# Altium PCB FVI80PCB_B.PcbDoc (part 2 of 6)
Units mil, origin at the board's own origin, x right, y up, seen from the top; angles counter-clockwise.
Board outline 3540 x 3115 mil, 12 copper layers (Top Layer, Int1(GND), Int2(Signal), Int3(GND), Int4(Signal), Int5 (GND&PW), Int6 (GND&PW), Int7(Signal), Int8(GND), Int9(Signal), Int10(GND), Bottom Layer), stack 77.136 mil thick; 488 components, 321 nets, 1809 pads, 882 vias.
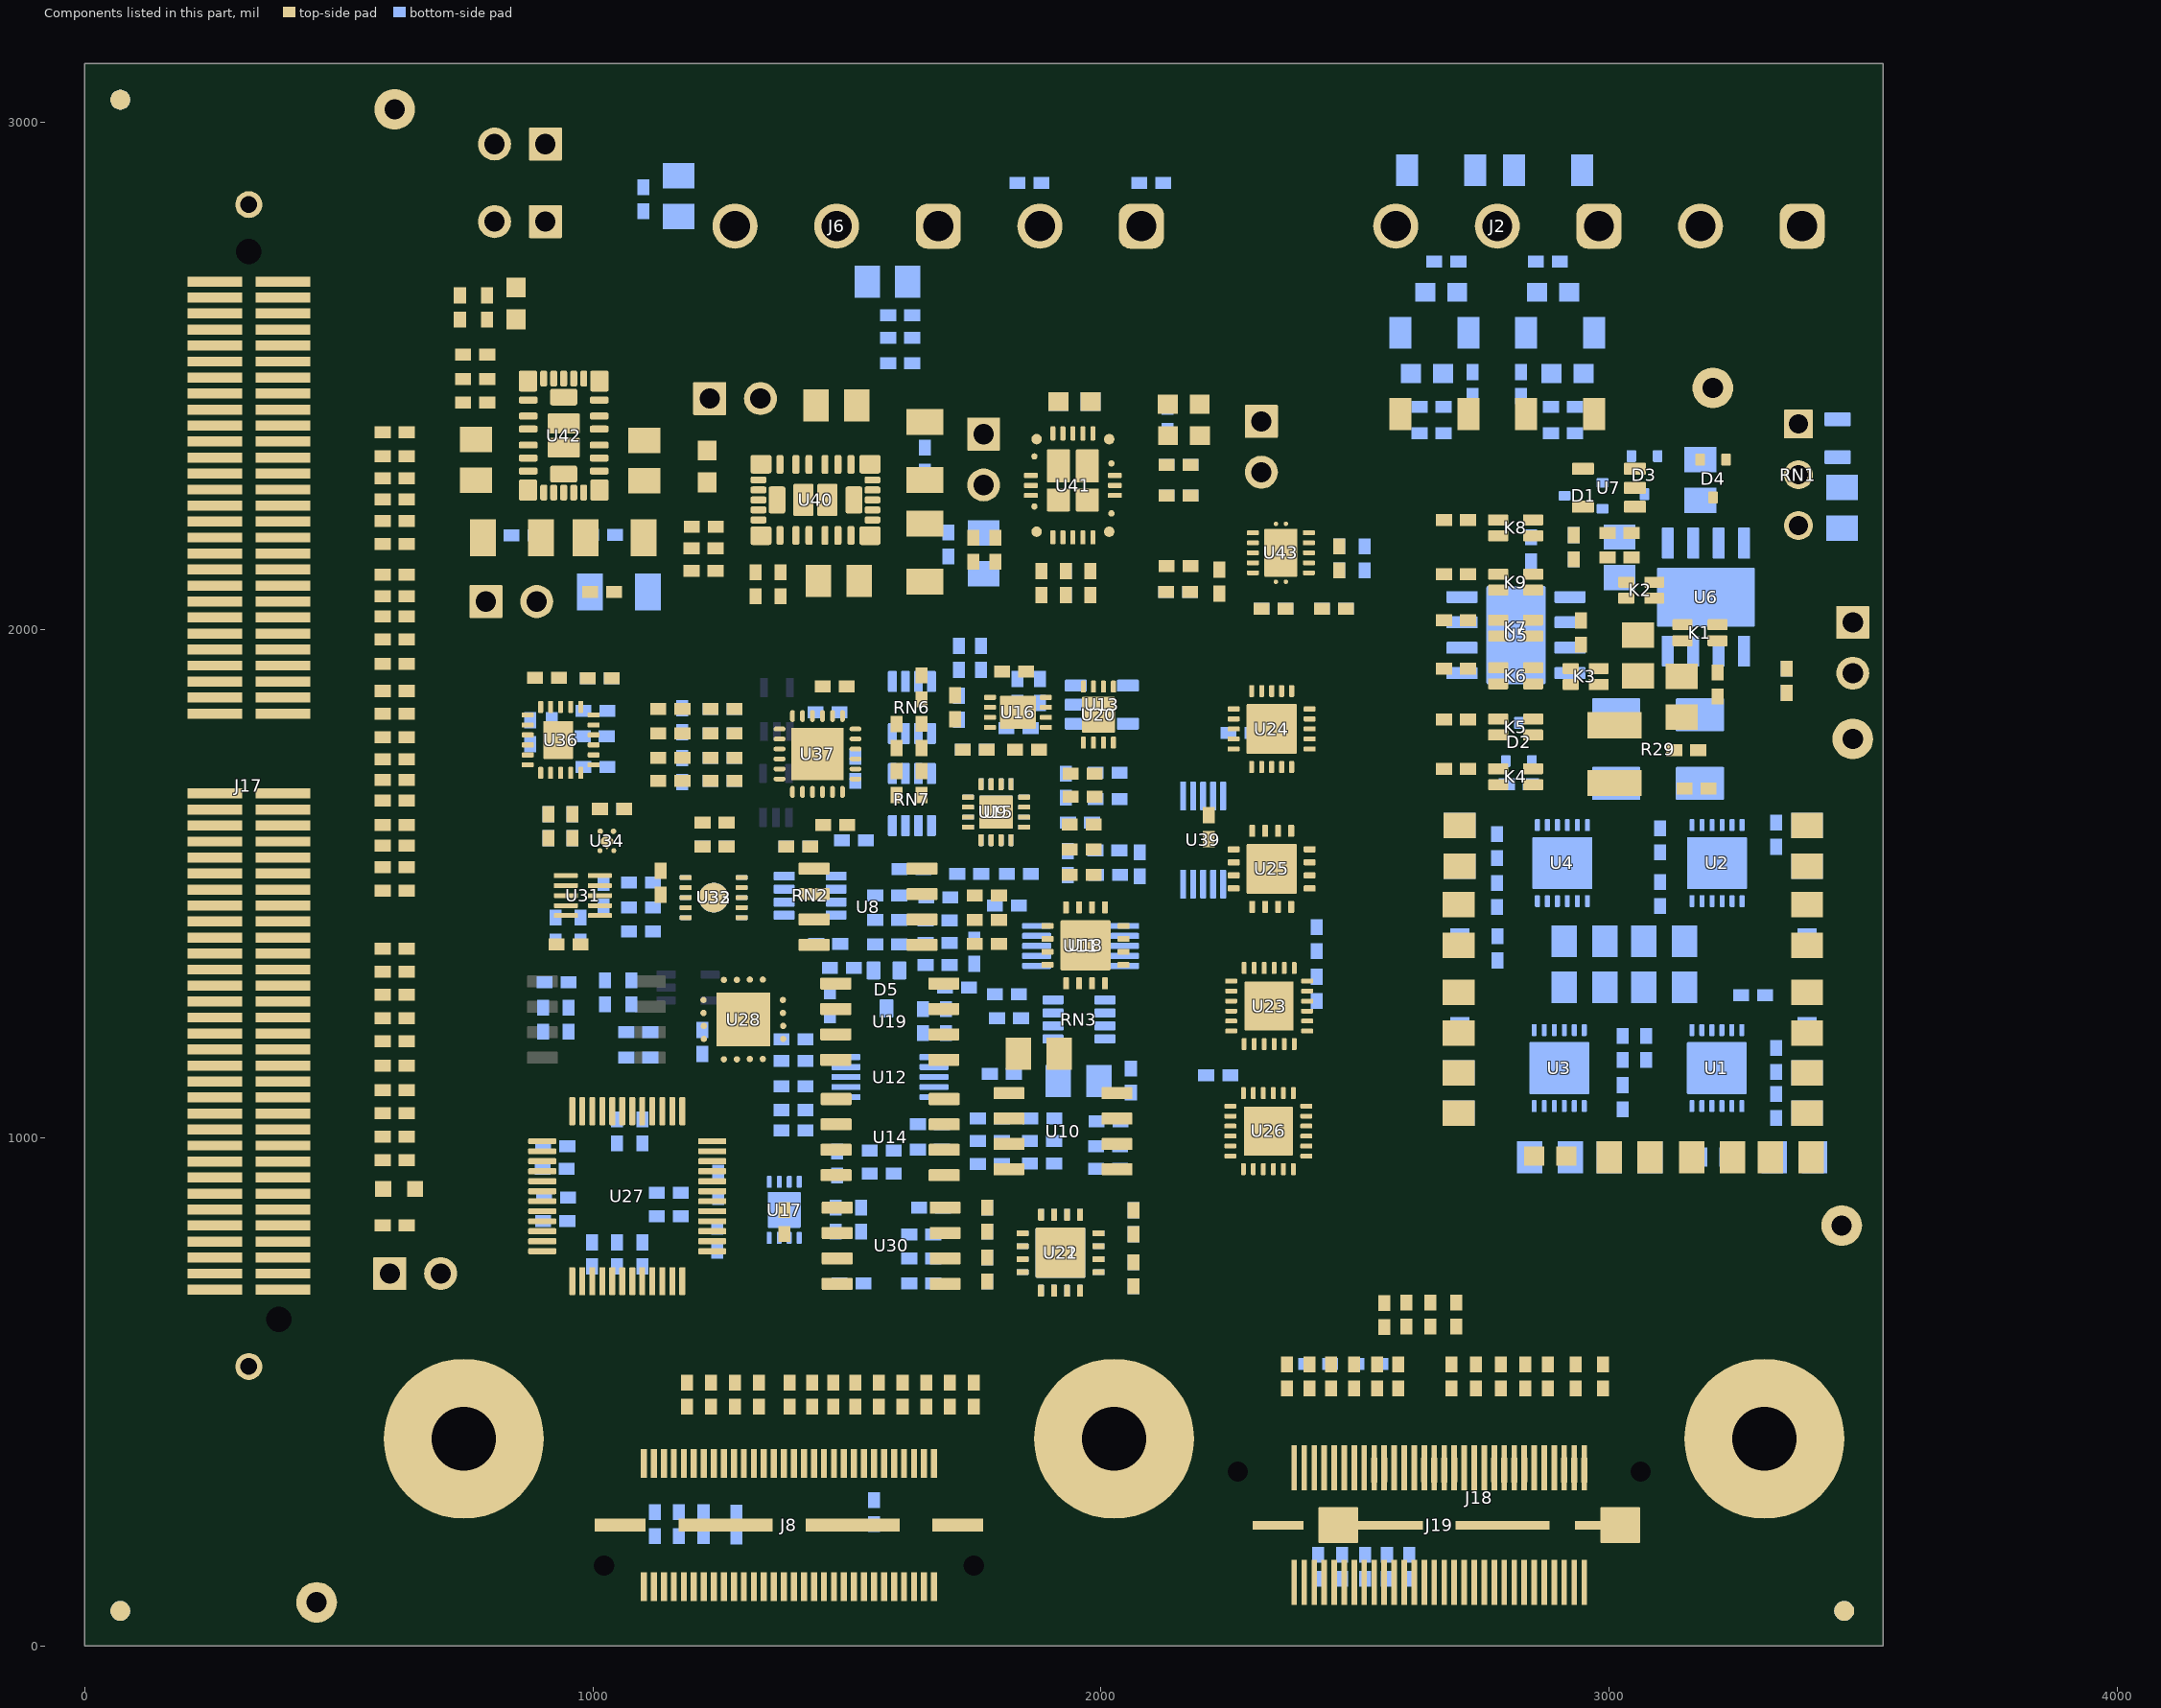
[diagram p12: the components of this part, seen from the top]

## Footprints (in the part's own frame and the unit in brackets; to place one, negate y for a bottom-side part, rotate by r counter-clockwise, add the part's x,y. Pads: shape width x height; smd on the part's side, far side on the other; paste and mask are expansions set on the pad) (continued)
DNT0012B-MFG [mm]
  rrect40% 0.6x0.25 smd paste+0 mask+0: 1(-1.9,1.25) 2(-1.9,0.75) 3(-1.9,0.25) 4(-1.9,-0.25) 5(-1.9,-0.75) 6(-1.9,-1.25) 7(1.9,-1.25) 8(1.9,-0.75) 9(1.9,-0.25) 10(1.9,0.25) 11(1.9,0.75) 12(1.9,1.25)
  rrect4% 2.6x3 smd paste-1000 mask+0: 13(0,0)
  silkscreen extent -2.87,-2.05 2.05,2.05, body extent -2,-2 2,2, height 1
DQN0004A-MFG [mm]
  round 0.279 smd paste-1000 mask-1000: 1(-0.505,0.33) 2(-0.505,-0.33)
  round 0.251 smd paste-1000 mask-1000: 3(0.459,-0.346) 4(0.459,0.346)
  rrect17% 0.58x0.58 smd rot 135 paste-1000 mask-1000: 5(0,0)
  Top Layer region: -0.66,-0.485 -0.2,-0.485 -0.2,-0.385 -0.41,-0.175 -0.66,-0.175
  Top Layer region: 0.66,0.485 0.2,0.485 0.2,0.385 0.41,0.175 0.66,0.175
  Top Layer region: 0.66,-0.485 0.2,-0.485 0.2,-0.385 0.41,-0.175 0.66,-0.175
  Top Layer region: -0.66,0.485 -0.2,0.485 -0.2,0.385 -0.41,0.175 -0.66,0.175
  silkscreen extent -1.35,-0.9 0.53,0.9, body extent -0.5,-0.5 0.5,0.5, height 0.4
DRC0010J-MFG [mm] "Recommended Land Pattern"
  rrect42% 0.6x0.24 smd paste+0 mask+0: 1(-1.4,1) 2(-1.4,0.5) 3(-1.4,0) 4(-1.4,-0.5) 5(-1.4,-1) 6(1.4,-1) 7(1.4,-0.5) 8(1.4,0) 9(1.4,0.5) 10(1.4,1)
  round 1.485 smd paste-1000 mask+0: 11(0,0)
  Top Layer region: -0.825,-1.15 -0.818,-1.175 -0.8,-1.193 -0.775,-1.2 -0.775,-1.2 -0.375,-1.2 -0.375,-1.65 -0.368,-1.675 -0.35,-1.693 -0.325,-1.7 -0.325,-1.7 -0.175,-1.7 -0.156,-1.696 -0.14,-1.685 -0.129,-1.669 -0.125,-1.65 -0.125,-1.65 -0.125,-1.2 0.125,-1.2 0.125,-1.65 0.129,-1.669 0.14,-1.685 0.156,-1.696 0.175,-1.7 0.175,-1.7 0.325,-1.7 0.35,-1.693 0.368,-1.675 0.375,-1.65 0.375,-1.65 0.375,-1.2 0.775,-1.2 0.8,-1.193 0.818,-1.175 0.825,-1.15 0.825,-1.15 0.825,1.15 0.818,1.175 0.8,1.193 0.775,1.2 0.775,1.2 0.375,1.2 0.375,1.65 0.368,1.675 0.35,1.693 0.325,1.7 0.325,1.7 0.175,1.7 0.156,1.696 0.14,1.685 0.129,1.669 0.125,1.65 0.125,1.65 0.125,1.2 -0.125,1.2 -0.125,1.65 -0.129,1.669 -0.14,1.685 -0.156,1.696 -0.175,1.7 -0.175,1.7 -0.325,1.7 -0.35,1.693 -0.368,1.675 -0.375,1.65 -0.375,1.65 -0.375,1.2 -0.775,1.2 -0.8,1.193 -0.818,1.175 -0.825,1.15 -0.825,1.15
  silkscreen extent -2.38,-1.55 1.55,1.55, body extent -1.5,-1.5 1.5,1.5, height 1
DRX0010A [mm] "WSON-10"
  rrect33% 1.2x0.24 smd: 1(-0.85,1) 2(-0.85,0.5) 3(-0.85,0) 4(-0.85,-0.5) 5(-0.85,-1) 6(0.85,-1) 7(0.85,-0.5) 8(0.85,0) 9(0.85,0.5) 10(0.85,1)
  silkscreen extent -1.8,-1.6 1.8,1.6, body extent -1.3,-1.3 1.3,1.3, height 0.81
DSC0010J-MFG [mm]
  rrect42% 0.6x0.24 smd paste+0 mask+0: 1(-1.4,1) 2(-1.4,0.5) 3(-1.4,0) 4(-1.4,-0.5) 5(-1.4,-1) 6(1.4,-1) 7(1.4,-0.5) 8(1.4,0) 9(1.4,0.5) 10(1.4,1)
  round 0.225 smd paste-1000 mask+0: 11(-0.25,-1.45) 11(-0.25,1.448) 11(0.25,-1.448) 11(0.25,1.45)
  rrect6% 1.65x2.4 smd paste-1000 mask+0: 11(0,0)
  Top Layer region: -0.375,1.2 -0.375,1.65 -0.371,1.669 -0.36,1.685 -0.344,1.696 -0.325,1.7 -0.325,1.7 -0.175,1.7 -0.156,1.696 -0.14,1.685 -0.129,1.669 -0.125,1.65 -0.125,1.65 -0.125,1.2
  Top Layer region: 0.125,1.2 0.125,1.65 0.129,1.669 0.14,1.685 0.156,1.696 0.175,1.7 0.175,1.7 0.325,1.7 0.344,1.696 0.36,1.685 0.371,1.669 0.375,1.65 0.375,1.65 0.375,1.2
  Top Layer region: -0.125,-1.2 -0.125,-1.65 -0.132,-1.675 -0.15,-1.693 -0.175,-1.7 -0.175,-1.7 -0.325,-1.7 -0.344,-1.696 -0.36,-1.685 -0.371,-1.669 -0.375,-1.65 -0.375,-1.65 -0.375,-1.2
  Top Layer region: 0.375,-1.2 0.375,-1.65 0.371,-1.669 0.36,-1.685 0.344,-1.696 0.325,-1.7 0.325,-1.7 0.175,-1.7 0.156,-1.696 0.14,-1.685 0.129,-1.669 0.125,-1.65 0.125,-1.65 0.125,-1.2
  silkscreen extent -2.4,-1.55 1.55,1.55, body extent -1.8,-1.8 1.8,1.8, height 0.25
FCC_disclaimer [mil]
Fiducial10-20 [mm]
  round 1 smd mask+0.5: 1(0,0)
  Top Layer keep-out circle w1.178: c0,0 r0.5
FP-CRCW08055K00FKTA_0805-MFG [mm]
  rrect14% 0.7x1.3 smd paste+0 mask+0: 1(-0.95,0) 2(0.95,0)
  silkscreen extent -0.23,-0.7 0.23,0.7, body extent -1,-0.63 1,0.63, height 0.5
FP-SBAV99WT1G_SOT-323-3-419-04-MFG [mm]
  rrect14% 0.9x0.7 smd paste+0 mask+0: 1(-0.95,0.65) 2(-0.95,-0.65) 3(0.95,0)
  silkscreen extent -0.13,-1.1 0.67,1.1, body extent -1.05,-1.05 1.05,1.05, height 1
FP-TLP3420(TP,F_SMD4-MFG [mm]
  rrect18% 0.55x1 smd paste+0 mask+0: 1(-0.4,-0.875) 2(0.4,-0.875) 3(0.4,0.875) 4(-0.4,0.875)
  silkscreen extent -1.07,-2.08 1.07,1.58, body extent -0.85,-1.48 0.85,1.48, height 0.25
FP-Y0115V0030VV9L_RADIAL-MFG [mm] "Recommended Land Pattern"
  rrect7% 1.45x1.45 hole 0.95 paste-2539.97 mask+0: 1(-2.54,0)
  round 1.45 hole 0.95 paste-2539.97 mask+0: 2(0,0) 3(2.54,0)
  silkscreen extent -5.15,-1.85 4.55,1.85, body extent -4.45,-1.75 4.45,1.75, height 10.7
FP-Y08502R00000F9R_2516-MFG [mm] "Recommended Land Pattern"
  rrect6% 2.41x1.65 smd paste+0 mask+0: E1(-2.095,1.715) E2(-2.095,-1.715) I1(2.095,1.715) I2(2.095,-1.715)
  silkscreen extent -4,-2.15 3.3,2.15, body extent -3.18,-2.03 3.18,2.03, height 1.02
Keystone5000 [mil] "For Keystone 500x miniature loop terminals"
  round 80 hole 40: 1(0,0)
  silkscreen extent -52,-52 52,52, body extent -49,-49 49,49, height 182
Keystone5001 [mil] "For Keystone 500x miniature loop terminals"
  round 80 hole 40: 1(0,0)
  silkscreen extent -52,-52 52,52, body extent -49,-49 49,49, height 182
Label_650x200 [mil] "Thermal Transfer Label"
  round 1 on Mech14: 0(0,0)
  silkscreen extent -325,-100 325,100, body extent -325,-100 325,100, height 1
"NY PMS 440 0025 PH" [mm] "4-40 nylon screw and mounting hole"
  round 8 / inner round 3.556 / far side round 8 hole 3.2: 1(0,0)
  body extent -3.3,-3.3 3.3,3.3, height 2.69
Omron_S-VSON4 [mm] "SMD, 4-Leads, Body 2x1.45mm"
  rrect18% 0.8x0.55 smd: 1(-0.65,0.4) 2(-0.65,-0.4)
  rrect18% 1x0.55 smd: 3(0.75,-0.4) 4(0.75,0.4)
  silkscreen extent -0.7,0.9 -0.6,1, body extent -0.9,-0.72 1.1,0.73, height 1.65
PFB0048A-MFG [mm]
  rrect33% 1.4x0.3 smd paste-1000 mask+0: 1(-4.25,2.75) 2(-4.25,2.25) 3(-4.25,1.75) 4(-4.25,1.25) 5(-4.25,0.75) 6(-4.25,0.25) 7(-4.25,-0.25) 8(-4.25,-0.75) 9(-4.25,-1.25) 10(-4.25,-1.75) 11(-4.25,-2.25) 12(-4.25,-2.75) 25(4.25,-2.75) 26(4.25,-2.25) 27(4.25,-1.75) 28(4.25,-1.25) 29(4.25,-0.75) 30(4.25,-0.25) 31(4.25,0.25) 32(4.25,0.75) 33(4.25,1.25) 34(4.25,1.75) 35(4.25,2.25) 36(4.25,2.75)
  rrect33% 0.3x1.4 smd paste-1000 mask+0: 13(-2.75,-4.25) 14(-2.25,-4.25) 15(-1.75,-4.25) 16(-1.25,-4.25) 17(-0.75,-4.25) 18(-0.25,-4.25) 19(0.25,-4.25) 20(0.75,-4.25) 21(1.25,-4.25) 22(1.75,-4.25) 23(2.25,-4.25) 24(2.75,-4.25) 37(2.75,4.25) 38(2.25,4.25) 39(1.75,4.25) 40(1.25,4.25) 41(0.75,4.25) 42(0.25,4.25) 43(-0.25,4.25) 44(-0.75,4.25) 45(-1.25,4.25) 46(-1.75,4.25) 47(-2.25,4.25) 48(-2.75,4.25)
  silkscreen extent -5.63,-3.6 3.6,3.6, body extent -5.05,-5.05 5.05,5.05, height 0.25
RDH0030A-MFG [mm]
  rrect22% 0.93x1.05 smd paste-1000 mask-1000: 1(-1.786,2.725) 8(-1.786,-2.725) 14(1.786,-2.725) 21(1.786,2.725)
  rrect57% 0.95x0.35 smd paste-1000 mask-1000: 2(-1.775,1.775) 3(-1.775,0.975) 4(-1.775,0.325) 5(-1.775,-0.475) 6(-1.775,-1.125) 7(-1.775,-1.775) 15(1.775,-1.775) 16(1.775,-1.125) 17(1.775,-0.475) 18(1.775,0.325) 19(1.775,0.975) 20(1.775,1.775)
  rrect57% 0.35x0.8 smd paste-1000 mask-1000: 9(-1,-2.85) 10(-0.5,-2.85) 11(0,-2.85) 12(0.5,-2.85) 13(1,-2.85) 22(1,2.85) 23(0.5,2.85) 24(0,2.85) 25(-0.5,2.85) 26(-1,2.85)
  rrect24% 1.35x0.84 smd paste-1000 mask-1000: 27(0,1.925) 30(0,-1.925)
  rrect10% 1.6x1 smd paste-1000 mask-1000: 28(0,0.6) 29(0,-0.6)
  Top Layer region: -0.85,1.05 -0.837,1.1 -0.8,1.137 -0.75,1.15 -0.75,1.15 0.75,1.15 0.8,1.137 0.837,1.1 0.85,1.05 0.85,1.05 0.85,-1.05 0.837,-1.1 0.8,-1.137 0.75,-1.15 0.75,-1.15 -0.75,-1.15 -0.8,-1.137 -0.837,-1.1 -0.85,-1.05 -0.85,-1.05
  silkscreen extent -2.95,-3.65 2.05,3.65, body extent -2.35,-3.35 2.35,3.35, height 0.25
RDU0028A-MFG [mm]
  round 0.52 smd paste+0 mask+0: 1(-1.814,2.314) 7(-1.814,-2.314) 13(1.814,-2.314) 19(1.814,2.314)
  round 0.315 smd paste+0 mask+0: 2(-1.925,1.4) 6(-1.925,-1.1) 14(1.925,-1.45) 18(1.925,1.05)
  rrect40% 0.7x0.25 smd paste+0 mask+0: 3(-2.1,0.5) 4(-2.1,0) 5(-2.1,-0.5) 15(2.1,-0.5) 16(2.1,0) 17(2.1,0.5)
  rrect40% 0.25x0.7 smd paste+0 mask+0: 8(-1,-2.6) 9(-0.5,-2.6) 10(0,-2.6) 11(0.5,-2.6) 12(1,-2.6) 20(1,2.6) 21(0.5,2.6) 22(0,2.6) 23(-0.5,2.6) 24(-1,2.6)
  rrect9% 1.15x1.15 smd paste-1000 mask+0: 25(-0.725,0.725) 28(0.725,0.725)
  rrect9% 1.15x1.65 smd paste-1000 mask+0: 26(-0.725,-0.975) 27(0.725,-0.975)
  Top Layer region: 2.4,0.875 1.8,0.875 1.775,0.882 1.757,0.9 1.75,0.925 1.75,0.925 1.75,1.575 1.754,1.594 1.765,1.61 1.781,1.621 1.8,1.625 1.8,1.625 2.4,1.625 2.419,1.621 2.435,1.61 2.446,1.594 2.45,1.575 2.45,1.575 2.45,1.425 2.443,1.4 2.425,1.382 2.4,1.375 2.4,1.375 2.225,1.375 2.187,1.367 2.154,1.346 2.133,1.313 2.125,1.275 2.125,1.275 2.125,1.225 2.138,1.175 2.175,1.138 2.225,1.125 2.225,1.125 2.4,1.125 2.419,1.121 2.435,1.11 2.446,1.094 2.45,1.075 2.45,1.075 2.45,0.925 2.443,0.9 2.425,0.882 2.4,0.875
  Top Layer region: 2.4,-1.625 1.8,-1.625 1.775,-1.618 1.757,-1.6 1.75,-1.575 1.75,-1.575 1.75,-0.925 1.754,-0.906 1.765,-0.89 1.781,-0.879 1.8,-0.875 1.8,-0.875 2.4,-0.875 2.419,-0.879 2.435,-0.89 2.446,-0.906 2.45,-0.925 2.45,-0.925 2.45,-1.075 2.443,-1.1 2.425,-1.118 2.4,-1.125 2.4,-1.125 2.225,-1.125 2.187,-1.133 2.154,-1.154 2.133,-1.187 2.125,-1.225 2.125,-1.225 2.125,-1.275 2.138,-1.325 2.175,-1.362 2.225,-1.375 2.225,-1.375 2.4,-1.375 2.419,-1.379 2.435,-1.39 2.446,-1.406 2.45,-1.425 2.45,-1.425 2.45,-1.575 2.443,-1.6 2.425,-1.618 2.4,-1.625
  Top Layer region: -2.4,-0.875 -1.8,-0.875 -1.775,-0.882 -1.757,-0.9 -1.75,-0.925 -1.75,-0.925 -1.75,-1.575 -1.754,-1.594 -1.765,-1.61 -1.781,-1.621 -1.8,-1.625 -1.8,-1.625 -2.4,-1.625 -2.419,-1.621 -2.435,-1.61 -2.446,-1.594 -2.45,-1.575 -2.45,-1.575 -2.45,-1.425 -2.443,-1.4 -2.425,-1.382 -2.4,-1.375 -2.4,-1.375 -2.225,-1.375 -2.187,-1.367 -2.154,-1.346 -2.133,-1.313 -2.125,-1.275 -2.125,-1.275 -2.125,-1.225 -2.138,-1.175 -2.175,-1.138 -2.225,-1.125 -2.225,-1.125 -2.4,-1.125 -2.419,-1.121 -2.435,-1.11 -2.446,-1.094 -2.45,-1.075 -2.45,-1.075 -2.45,-0.925 -2.443,-0.9 -2.425,-0.882 -2.4,-0.875
  Top Layer region: -2.4,1.625 -1.8,1.625 -1.781,1.621 -1.765,1.61 -1.754,1.594 -1.75,1.575 -1.75,1.575 -1.75,0.925 -1.754,0.906 -1.765,0.89 -1.781,0.879 -1.8,0.875 -1.8,0.875 -2.4,0.875 -2.419,0.879 -2.435,0.89 -2.446,0.906 -2.45,0.925 -2.45,0.925 -2.45,1.075 -2.443,1.1 -2.425,1.118 -2.4,1.125 -2.4,1.125 -2.225,1.125 -2.187,1.133 -2.154,1.154 -2.133,1.187 -2.125,1.225 -2.125,1.225 -2.125,1.275 -2.138,1.325 -2.175,1.362 -2.225,1.375 -2.225,1.375 -2.4,1.375 -2.419,1.379 -2.435,1.39 -2.446,1.406 -2.45,1.425 -2.45,1.425 -2.45,1.575 -2.443,1.6 -2.425,1.618 -2.4,1.625
  Top Layer region: 1.575,2.95 1.55,2.943 1.532,2.925 1.525,2.9 1.525,2.9 1.525,2.075 1.529,2.056 1.54,2.04 1.556,2.029 1.575,2.025 1.575,2.025 2.4,2.025 2.423,2.033 2.439,2.051 2.445,2.075 2.445,2.075 2.45,2.225 2.443,2.25 2.425,2.268 2.4,2.275 2.4,2.275 2.225,2.275 2.187,2.283 2.154,2.304 2.133,2.337 2.125,2.375 2.125,2.375 2.125,2.575 2.118,2.6 2.1,2.618 2.075,2.625 2.075,2.625 1.875,2.625 1.837,2.633 1.804,2.654 1.783,2.687 1.775,2.725 1.775,2.725 1.775,2.9 1.768,2.925 1.75,2.943 1.725,2.95 1.725,2.95
  Top Layer region: 1.575,-2.95 1.55,-2.943 1.532,-2.925 1.525,-2.9 1.525,-2.9 1.525,-2.075 1.529,-2.056 1.54,-2.04 1.556,-2.029 1.575,-2.025 1.575,-2.025 2.4,-2.025 2.423,-2.033 2.439,-2.051 2.445,-2.075 2.445,-2.075 2.45,-2.225 2.443,-2.25 2.425,-2.268 2.4,-2.275 2.4,-2.275 2.225,-2.275 2.187,-2.283 2.154,-2.304 2.133,-2.337 2.125,-2.375 2.125,-2.375 2.125,-2.575 2.118,-2.6 2.1,-2.618 2.075,-2.625 2.075,-2.625 1.875,-2.625 1.837,-2.633 1.804,-2.654 1.783,-2.687 1.775,-2.725 1.775,-2.725 1.775,-2.9 1.768,-2.925 1.75,-2.943 1.725,-2.95 1.725,-2.95
  Top Layer region: -1.575,-2.95 -1.55,-2.943 -1.532,-2.925 -1.525,-2.9 -1.525,-2.9 -1.525,-2.075 -1.529,-2.056 -1.54,-2.04 -1.556,-2.029 -1.575,-2.025 -1.575,-2.025 -2.4,-2.025 -2.423,-2.033 -2.439,-2.051 -2.445,-2.075 -2.445,-2.075 -2.45,-2.225 -2.443,-2.25 -2.425,-2.268 -2.4,-2.275 -2.4,-2.275 -2.225,-2.275 -2.187,-2.283 -2.154,-2.304 -2.133,-2.337 -2.125,-2.375 -2.125,-2.375 -2.125,-2.575 -2.118,-2.6 -2.1,-2.618 -2.075,-2.625 -2.075,-2.625 -1.875,-2.625 -1.837,-2.633 -1.804,-2.654 -1.783,-2.687 -1.775,-2.725 -1.775,-2.725 -1.775,-2.9 -1.768,-2.925 -1.75,-2.943 -1.725,-2.95 -1.725,-2.95
  Top Layer region: -1.575,2.95 -1.55,2.943 -1.532,2.925 -1.525,2.9 -1.525,2.9 -1.525,2.075 -1.529,2.056 -1.54,2.04 -1.556,2.029 -1.575,2.025 -1.575,2.025 -2.4,2.025 -2.423,2.033 -2.439,2.051 -2.445,2.075 -2.445,2.075 -2.45,2.225 -2.443,2.25 -2.425,2.268 -2.4,2.275 -2.4,2.275 -2.225,2.275 -2.187,2.283 -2.154,2.304 -2.133,2.337 -2.125,2.375 -2.125,2.375 -2.125,2.575 -2.118,2.6 -2.1,2.618 -2.075,2.625 -2.075,2.625 -1.875,2.625 -1.837,2.633 -1.804,2.654 -1.783,2.687 -1.775,2.725 -1.775,2.725 -1.775,2.9 -1.768,2.925 -1.75,2.943 -1.725,2.95 -1.725,2.95
  silkscreen extent -3.2,-3.13 2.63,3.13, body extent -2.55,-3.05 2.55,3.05, height 0.25
RGT0016J-MFG [mm]
  rrect40% 0.6x0.25 smd paste+0 mask+0: 1(-1.4,0.75) 2(-1.4,0.25) 3(-1.4,-0.25) 4(-1.4,-0.75) 9(1.4,-0.75) 10(1.4,-0.25) 11(1.4,0.25) 12(1.4,0.75)
  rrect40% 0.25x0.6 smd paste+0 mask+0: 5(-0.75,-1.4) 6(-0.25,-1.4) 7(0.25,-1.4) 8(0.75,-1.4) 13(0.75,1.4) 14(0.25,1.4) 15(-0.25,1.4) 16(-0.75,1.4)
  rrect6% 1.66x1.66 smd paste-1000 mask+0: 17(0,0)
  silkscreen extent -2.37,-1.55 1.55,1.55, body extent -1.5,-1.5 1.5,1.5, height 1
RQX0008A-MFG [mm] "Recommended Land Pattern"
  rrect40% 0.6x0.25 smd paste+0 mask+0: 1(-1.4,0.75) 2(-1.4,0.25) 3(-1.4,-0.25) 4(-1.4,-0.75) 5(1.4,-0.75) 6(1.4,-0.25) 7(1.4,0.25) 8(1.4,0.75)
  rrect6% 1.8x1.65 smd paste-1000 mask+0: 9(0,0)
  silkscreen extent -2.45,-1.33 1.5,1.33, body extent -1.5,-1 1.5,1, height 0.8
RRQ0020A-MFG [mm]
  rrect40% 0.6x0.25 smd paste+0 mask+0: 1(-1.9,1) 2(-1.9,0.5) 3(-1.9,0) 4(-1.9,-0.5) 5(-1.9,-1) 11(1.9,-1) 12(1.9,-0.5) 13(1.9,0) 14(1.9,0.5) 15(1.9,1)
  rrect40% 0.25x0.6 smd paste+0 mask+0: 6(-1,-1.9) 7(-0.5,-1.9) 8(0,-1.9) 9(0.5,-1.9) 10(1,-1.9) 16(1,1.9) 17(0.5,1.9) 18(0,1.9) 19(-0.5,1.9) 20(-1,1.9)
  rrect4% 2.5x2.5 smd paste-1000 mask+0: 21(0,0)
  silkscreen extent -2.88,-2.05 2.05,2.05, body extent -2.3,-2.3 2.3,2.3, height 0.25
RTW0024A [mm] "QFN, 24-Leads, Body 4x4mm, Pitch 0.5mm, Thermal Pad 2.6x2.6mm, TI Recommended"
  oval 0.6x0.24 smd: 1(-1.9,1.25) 2(-1.9,0.75) 3(-1.9,0.25) 4(-1.9,-0.25) 5(-1.9,-0.75) 6(-1.9,-1.25) 13(1.9,-1.25) 14(1.9,-0.75) 15(1.9,-0.25) 16(1.9,0.25) 17(1.9,0.75) 18(1.9,1.25)
  oval 0.24x0.6 smd: 7(-1.25,-1.9) 8(-0.75,-1.9) 9(-0.25,-1.9) 10(0.25,-1.9) 11(0.75,-1.9) 12(1.25,-1.9) 19(1.25,1.9) 20(0.75,1.9) 21(0.25,1.9) 22(-0.25,1.9) 23(-0.75,1.9) 24(-1.25,1.9)
  rect 2.6x2.6 smd paste-1.3: 25(0,0)
  silkscreen extent -2.22,-2.22 2.22,2.22, body extent -2.07,-2.07 2.07,2.07, height 0.81
RTW0024B-MFG [mm]
  rrect42% 0.6x0.24 smd paste+0 mask+0: 1(-1.9,1.25) 2(-1.9,0.75) 3(-1.9,0.25) 4(-1.9,-0.25) 5(-1.9,-0.75) 6(-1.9,-1.25) 13(1.9,-1.25) 14(1.9,-0.75) 15(1.9,-0.25) 16(1.9,0.25) 17(1.9,0.75) 18(1.9,1.25)
  rrect42% 0.24x0.6 smd paste+0 mask+0: 7(-1.25,-1.9) 8(-0.75,-1.9) 9(-0.25,-1.9) 10(0.25,-1.9) 11(0.75,-1.9) 12(1.25,-1.9) 19(1.25,1.9) 20(0.75,1.9) 21(0.25,1.9) 22(-0.25,1.9) 23(-0.75,1.9) 24(-1.25,1.9)
  rrect4% 2.45x2.45 smd paste-1000 mask+0: 25(0,0)
  silkscreen extent -2.9,-2.05 2.05,2.05, body extent -2.3,-2.3 2.3,2.3, height 0.25
RUM0016B-MFG [mm] "Recommended Land Pattern"
  round 0.315 smd paste-1000 mask+0: 1(-1.993,0.975) 2(-1.993,0.325) 3(-1.975,-0.325) 4(-1.975,-0.975) 5(-0.975,-1.993) 6(-0.325,-1.993) 7(0.325,-1.975) 8(0.975,-1.975) 9(1.993,-0.975) 10(1.993,-0.325) 11(1.975,0.325) 12(1.975,0.975) 13(0.975,1.993) 14(0.325,1.993) 15(-0.325,1.975) 16(-0.975,1.975)
  rrect4% 2.7x2.7 smd paste-1000 mask+0: 17(0,0)
  Top Layer region: -2.4,1.15 -1.725,1.15 -1.658,1.137 -1.601,1.099 -1.563,1.042 -1.55,0.975 -1.55,0.975 -1.563,0.908 -1.601,0.851 -1.658,0.813 -1.725,0.8 -1.725,0.8 -2.4,0.8
  Top Layer region: -2.4,0.5 -1.725,0.5 -1.658,0.487 -1.601,0.449 -1.563,0.392 -1.55,0.325 -1.55,0.325 -1.563,0.258 -1.601,0.201 -1.658,0.163 -1.725,0.15 -1.725,0.15 -2.4,0.15
  Top Layer region: -2.4,-0.15 -1.725,-0.15 -1.658,-0.163 -1.601,-0.201 -1.563,-0.258 -1.55,-0.325 -1.55,-0.325 -1.563,-0.392 -1.601,-0.449 -1.658,-0.487 -1.725,-0.5 -1.725,-0.5 -2.4,-0.5
  Top Layer region: -2.4,-0.8 -1.725,-0.8 -1.658,-0.813 -1.601,-0.851 -1.563,-0.908 -1.55,-0.975 -1.55,-0.975 -1.563,-1.042 -1.601,-1.099 -1.658,-1.137 -1.725,-1.15 -1.725,-1.15 -2.4,-1.15
  Top Layer region: 2.4,-1.15 1.725,-1.15 1.658,-1.137 1.601,-1.099 1.563,-1.042 1.55,-0.975 1.55,-0.975 1.563,-0.908 1.601,-0.851 1.658,-0.813 1.725,-0.8 1.725,-0.8 2.4,-0.8
  Top Layer region: 2.4,-0.5 1.725,-0.5 1.658,-0.487 1.601,-0.449 1.563,-0.392 1.55,-0.325 1.55,-0.325 1.563,-0.258 1.601,-0.201 1.658,-0.163 1.725,-0.15 1.725,-0.15 2.4,-0.15
  Top Layer region: 2.4,0.15 1.725,0.15 1.658,0.163 1.601,0.201 1.563,0.258 1.55,0.325 1.55,0.325 1.563,0.392 1.601,0.449 1.658,0.487 1.725,0.5 1.725,0.5 2.4,0.5
  Top Layer region: 2.4,0.8 1.725,0.8 1.658,0.813 1.601,0.851 1.563,0.908 1.55,0.975 1.55,0.975 1.563,1.042 1.601,1.099 1.658,1.137 1.725,1.15 1.725,1.15 2.4,1.15
  Top Layer region: -1.15,-2.4 -1.15,-1.725 -1.137,-1.658 -1.099,-1.601 -1.042,-1.563 -0.975,-1.55 -0.975,-1.55 -0.908,-1.563 -0.851,-1.601 -0.813,-1.658 -0.8,-1.725 -0.8,-1.725 -0.8,-2.4
  Top Layer region: -0.5,-2.4 -0.5,-1.725 -0.487,-1.658 -0.449,-1.601 -0.392,-1.563 -0.325,-1.55 -0.325,-1.55 -0.258,-1.563 -0.201,-1.601 -0.163,-1.658 -0.15,-1.725 -0.15,-1.725 -0.15,-2.4
  Top Layer region: 0.15,-2.4 0.15,-1.725 0.163,-1.658 0.201,-1.601 0.258,-1.563 0.325,-1.55 0.325,-1.55 0.392,-1.563 0.449,-1.601 0.487,-1.658 0.5,-1.725 0.5,-1.725 0.5,-2.4
  Top Layer region: 0.8,-2.4 0.8,-1.725 0.813,-1.658 0.851,-1.601 0.908,-1.563 0.975,-1.55 0.975,-1.55 1.042,-1.563 1.099,-1.601 1.137,-1.658 1.15,-1.725 1.15,-1.725 1.15,-2.4
  Top Layer region: 1.15,2.4 1.15,1.725 1.137,1.658 1.099,1.601 1.042,1.563 0.975,1.55 0.975,1.55 0.908,1.563 0.851,1.601 0.813,1.658 0.8,1.725 0.8,1.725 0.8,2.4
  Top Layer region: 0.5,2.4 0.5,1.725 0.487,1.658 0.449,1.601 0.392,1.563 0.325,1.55 0.325,1.55 0.258,1.563 0.201,1.601 0.163,1.658 0.15,1.725 0.15,1.725 0.15,2.4
  Top Layer region: -0.15,2.4 -0.15,1.725 -0.163,1.658 -0.201,1.601 -0.258,1.563 -0.325,1.55 -0.325,1.55 -0.392,1.563 -0.449,1.601 -0.487,1.658 -0.5,1.725 -0.5,1.725 -0.5,2.4
  Top Layer region: -0.8,2.4 -0.8,1.725 -0.813,1.658 -0.851,1.601 -0.908,1.563 -0.975,1.55 -0.975,1.55 -1.042,1.563 -1.099,1.601 -1.137,1.658 -1.15,1.725 -1.15,1.725 -1.15,2.4
  Top Layer keep-out region: -2,1.5 -1.5,1.5 -1.5,2 -2,2
  silkscreen extent -3.07,-2.05 2.05,2.05, body extent -2,-2 2,2, height 0.8
RUM0016E-MFG#1 [mm]
  rrect33% 0.6x0.3 smd paste+0 mask+0: 1(-1.9,0.975) 2(-1.9,0.325) 3(-1.9,-0.325) 4(-1.9,-0.975) 9(1.9,-0.975) 10(1.9,-0.325) 11(1.9,0.325) 12(1.9,0.975)
  rrect33% 0.3x0.6 smd paste+0 mask+0: 5(-0.975,-1.9) 6(-0.325,-1.9) 7(0.325,-1.9) 8(0.975,-1.9) 13(0.975,1.9) 14(0.325,1.9) 15(-0.325,1.9) 16(-0.975,1.9)
  rrect4% 2.5x2.5 smd paste-25.4 mask+0: 17(0,0)
  silkscreen extent -2.9,-2.05 2.05,2.05, body extent -2,-2 2,2, height 0.8
RUM0016E-MFG#2 [mm]
  rrect33% 0.6x0.3 smd paste+0 mask+0: 1(-1.9,0.975) 2(-1.9,0.325) 3(-1.9,-0.325) 4(-1.9,-0.975) 9(1.9,-0.975) 10(1.9,-0.325) 11(1.9,0.325) 12(1.9,0.975)
  rrect33% 0.3x0.6 smd paste+0 mask+0: 5(-0.975,-1.9) 6(-0.325,-1.9) 7(0.325,-1.9) 8(0.975,-1.9) 13(0.975,1.9) 14(0.325,1.9) 15(-0.325,1.9) 16(-0.975,1.9)
  rrect4% 2.5x2.5 smd paste-1000 mask+0: 17(0,0)
  silkscreen extent -2.9,-2.05 2.05,2.05, body extent -2,-2 2,2, height 0.8
Samtec_HTSW-102-07-G-S [mm] "Samtec 100mil, 1x2, 230 mil above insulator"
  rrect6% 1.65x1.65 hole 1.016: 1(-1.27,0)
  round 1.65 hole 1.016: 2(1.27,0)
  silkscreen extent -3.3,-1.27 2.54,1.27, body extent -2.54,-1.27 2.54,1.27, height 8.38
Samtec_QSH-030-01-X-D-A [mm] "Receptacle, 0.5 mm, 30x2, TH"
  rect 2.27x0.279 smd: 1(-2.865,7.25) 2(2.865,7.25) 3(-2.865,6.75) 4(2.865,6.75) 5(-2.865,6.25) 6(2.865,6.25) 7(-2.865,5.75) 8(2.865,5.75) 9(-2.865,5.25) 10(2.865,5.25) 11(-2.865,4.75) 12(2.865,4.75) 13(-2.865,4.25) 14(2.865,4.25) 15(-2.865,3.75) 16(2.865,3.75) 17(-2.865,3.25) 18(2.865,3.25) 19(-2.865,2.75) 20(2.865,2.75) 21(-2.865,2.25) 22(2.865,2.25) 23(-2.865,1.75) 24(2.865,1.75) 25(-2.865,1.25) 26(2.865,1.25) 27(-2.865,0.75) 28(2.865,0.75) 29(-2.865,0.25) 30(2.865,0.25) 31(-2.865,-0.25) 32(2.865,-0.25) 33(-2.865,-0.75) 34(2.865,-0.75) 35(-2.865,-1.25) 36(2.865,-1.25) 37(-2.865,-1.75) 38(2.865,-1.75) 39(-2.865,-2.25) 40(2.865,-2.25) 41(-2.865,-2.75) 42(2.865,-2.75) 43(-2.865,-3.25) 44(2.865,-3.25) 45(-2.865,-3.75) 46(2.865,-3.75) 47(-2.865,-4.25) 48(2.865,-4.25) 49(-2.865,-4.75) 50(2.865,-4.75) 51(-2.865,-5.25) 52(2.865,-5.25) 53(-2.865,-5.75) 54(2.865,-5.75) 55(-2.865,-6.25) 56(2.865,-6.25) 57(-2.865,-6.75) 58(2.865,-6.75) 59(-2.865,-7.25) 60(2.865,-7.25)
  round 0 hole 1.02 unplated: MH1(2.67,10.065) MH2(2.67,-10.065)
  rect 0.43x2.54 smd: MP1(0,8.065) MP4(0,-8.065)
  rect 0.43x4.7 smd: MP2(0,3.175) MP3(0,-3.175)
  silkscreen extent -3.9,-10.66 3.62,10.66, body extent -3.75,-10.64 3.75,10.67, height 3.25
Samtec_QTH-030-01-x-D-A [mil] "Header (Shrouded), 19.7mil, 30x2, SMT"
  rect 12x57 smd: 1(-285.7,121.5) 2(-285.7,-121.5) 3(-266,121.5) 4(-266,-121.5) 5(-246.3,121.5) 6(-246.3,-121.5) 7(-226.6,121.5) 8(-226.6,-121.5) 9(-206.9,121.5) 10(-206.9,-121.5) 11(-187.2,121.5) 12(-187.2,-121.5) 13(-167.5,121.5) 14(-167.5,-121.5) 15(-147.8,121.5) 16(-147.8,-121.5) 17(-128.1,121.5) 18(-128.1,-121.5) 19(-108.4,121.5) 20(-108.4,-121.5) 21(-88.7,121.5) 22(-88.7,-121.5) 23(-69,121.5) 24(-69,-121.5) 25(-49.3,121.5) 26(-49.3,-121.5) 27(-29.6,121.5) 28(-29.6,-121.5) 29(-9.9,121.5) 30(-9.9,-121.5) 31(9.8,121.5) 32(9.8,-121.5) 33(29.5,121.5) 34(29.5,-121.5) 35(49.2,121.5) 36(49.2,-121.5) 37(68.9,121.5) 38(68.9,-121.5) 39(88.6,121.5) 40(88.6,-121.5) 41(108.3,121.5) 42(108.3,-121.5) 43(128,121.5) 44(128,-121.5) 45(147.7,121.5) 46(147.7,-121.5) 47(167.4,121.5) 48(167.4,-121.5) 49(187.1,121.5) 50(187.1,-121.5) 51(206.8,121.5) 52(206.8,-121.5) 53(226.5,121.5) 54(226.5,-121.5) 55(246.2,121.5) 56(246.2,-121.5) 57(265.9,121.5) 58(265.9,-121.5) 59(285.6,121.5) 60(285.6,-121.5)
  round 0 hole 40 unplated: MH1(-364,80) MH2(364,80)
  rect 100x25 smd: MP1(-332.7,0) MP4(332.3,0)
  rect 185x25 smd: MP2(-125.2,0) MP3(124.8,0)
  silkscreen extent -394,-118 394,131, body extent -394,-140 394,140, height 170
SOT-323 [mm] "Diodes Inc recommended land pattern.  2016-02-24"
  rrect21% 0.6x0.47 smd: 1(-0.95,0.65) 2(-0.95,-0.65) 3(0.95,0)
  silkscreen extent -1.14,-1.22 0.77,1.22, body extent -1.13,-1.13 1.12,1.12, height 1.13
TI_Stacked_Overlay_Small [mil]
  silkscreen extent -418,-98 418,98
VAE0022A-MFG [mm]
  rrect40% 0.6x0.25 smd paste+0 mask+0: 1(-1.65,1.25) 2(-1.65,0.75) 3(-1.65,0.25) 4(-1.65,-0.25) 5(-1.65,-0.75) 6(-1.65,-1.25) 12(1.65,-1.25) 13(1.65,-0.75) 14(1.65,-0.25) 15(1.65,0.25) 16(1.65,0.75) 17(1.65,1.25)
  rrect40% 0.25x0.6 smd paste+0 mask+0: 7(-1,-1.65) 8(-0.5,-1.65) 9(0,-1.65) 10(0.5,-1.65) 11(1,-1.65) 18(1,1.65) 19(0.5,1.65) 20(0,1.65) 21(-0.5,1.65) 22(-1,1.65)
  rrect7% 1.5x1.895 smd paste-1000 mask+0: 23(0.123,0)
  silkscreen extent -2.63,-1.8 1.8,1.8, body extent -2.05,-2.05 2.05,2.05, height 0.25
WEEE_Minimum [mil] "WEEElie bin"
  silkscreen extent -95,-172 99,104
WL-SMCW_GREEN [mm] "WURTH"
  rect 0.8x0.8 smd: 1(-0.8,0) 2(0.8,0)
  silkscreen extent -1.9,-0.8 1.2,0.8, body extent -0.85,-0.45 0.85,0.45, height 0.8
Wurth_60900213421 [mil] "Shunt, 2.54mm, Black"
  round 1 on Mech3: 0(0,0)
  body extent -98,-48 98,48, height 338
Wurth_687122149022 [mm] "FPC Connector, 0.5mm, 22 Pos, R/A, SMT"
  rrect33% 0.3x1.3 smd: 1(-5.25,2.75) 2(-4.75,2.75) 3(-4.25,2.75) 4(-3.75,2.75) 5(-3.25,2.75) 6(-2.75,2.75) 7(-2.25,2.75) 8(-1.75,2.75) 9(-1.25,2.75) 10(-0.75,2.75) 11(-0.25,2.75) 12(0.25,2.75) 13(0.75,2.75) 14(1.25,2.75) 15(1.75,2.75) 16(2.25,2.75) 17(2.75,2.75) 18(3.25,2.75) 19(3.75,2.75) 20(4.25,2.75) 21(4.75,2.75) 22(5.25,2.75)
  rrect6% 2x1.8 smd: MP1(-7.05,0) MP2(7.05,0)
  body extent -7.55,-3.5 7.55,3, height 2.25
Wurth_691236510002 [mm] "Terminal Block, 5.08mm, 2x1, R/A, TH"
  rrect50% 2.25x2.25 hole 1.5: 1(-2.54,0)
  round 2.25 hole 1.5: 2(2.54,0)
  body extent -5.68,-5.5 5.08,5.85, height 18
Wurth_691236510003 [mm] "Terminal Block, 5.08mm, 3x1, R/A, TH"
  rrect50% 2.25x2.25 hole 1.5: 1(-5.08,0)
  round 2.25 hole 1.5: 2(0,0) 3(5.08,0)
  body extent -8.22,-5.5 7.62,5.85, height 18

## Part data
C1 C2 C3 C4 C5 C6 C7 C8 C10 C11 C15 C16 C141 C143: library part CMP-0006618-2, "CAP, CERM, 0.1 uF, 100 V, +/- 10%, X5R, 0402", Cap_Case=0402, Manufacturer=MuRata, Supplier Part Number 1=490-10458-1-ND, TempCo=X5R, Tolerance_%=10%, Value1=Unknown, Value2=100V, ValueDisplayed=0.1uF
C9 C13 C14 C18 C140 C142: library part CMP-0078499-1, "CAP, CERM, 4.7 µF, 100 V,+/- 20%, X7S, 1206", Cap_Case=1206, Manufacturer=AVX, Supplier Part Number 1=478-8719-1-ND, TempCo=X7S, Tolerance_%=20%, Value2=100V, ValueDisplayed=4.7µF
C12 C17: library part CMP-0006704-2, "CAP, CERM, 2200 pF, 100 V, +/- 10%, X7R, 0402", Cap_Case=0402, Manufacturer=MuRata, Supplier Part Number 1=GRM155R72A222KA01D-ND, TempCo=X7R, Tolerance_%=10%, Value1=Unknown, Value2=100V, ValueDisplayed=2200pF
C19 C20 C27 C28 C35 C36 C37 C38 C46 C52 C53 C56: library part CMP-0006443-2, "CAP, CERM, 27 pF, 50 V, +/- 5%, C0G/NP0, 0402", Cap_Case=0402, Manufacturer=MuRata, Supplier Part Number 1=14T3294, TempCo=C0G/NP0, Tolerance_%=5%, Value1=Unknown, Value2=50V, ValueDisplayed=27pF
C21 C22 C23 C24 C25 C26 C29 C30 C31 C32 C33 C34 C42 C43 C44 C45 C48 C49 C55 C57 C59 C60 C61 C62 C63 C64 C66 C67 C68 C69 C71 C72 C76 C78 C80 C85 C87 C89 C92 C96 C102 C104 C114 C117 C119 C120 C124 C127 C129 C131 C144 C145 C146 C147 C148 C149 C150: library part CMP-0080610-1, "CAP, CERM, 0.1 µF, 25 V,+/- 10%, X7R, AEC-Q200 Grade 1, 0402", Cap_Case=0402, Manufacturer=TDK, Supplier Part Number 1=445-6902-1-ND, TempCo=X7R, Tolerance_%=10%, Value2=25V, ValueDisplayed=0.1µF
C39 C86 C88 C91 C94 C95 C97 C98 C105 C109 C115 C122 C130 C134 C151 C152: library part CMP-0860997-1, "CAP, CERM, 1000 pF, 50 V,+/- 10%, X8R, AEC-Q200 Grade 0, 0402", Cap_Case=0402, Manufacturer=TDK, TempCo=X8R, Tolerance_%=10%, Value2=50V, ValueDisplayed=1000pF
C40 C106 C108 C133: library part CMP-0006674-2, "CAP, CERM, 0.01 uF, 50 V, +/- 10%, X7R, 0402", Cap_Case=0402, Manufacturer=MuRata, Supplier Part Number 1=490-4516-1-ND, TempCo=X7R, Tolerance_%=10%, Value1=Unknown, Value2=50V, ValueDisplayed=0.01uF
C41: library part CMP-0064928-2, "CAP, CERM, 0.47 uF, 25 V,+/- 10%, X5R, 0402", Cap_Case=0402, Manufacturer=MuRata, Supplier Part Number 1=490-14365-1-ND, TempCo=X5R, Tolerance_%=10%, Value1=Unknown, Value2=25V, ValueDisplayed=0.47uF
C47 C50 C51 C54 C58 C65 C70 C75 C77 C79 C90 C93 C116 C118 C128 C137: library part CMP-0006564-3, "CAP, CERM, 10 uF, 10 V, +/- 20%, X5R, 0402", Cap_Case=0402, Manufacturer=MuRata, TempCo=X5R, Tolerance_%=20%, Value1=Unknown, Value2=10V, ValueDisplayed=10uF
C99 C121: library part CMP-0081259-1, "CAP, CERM, 1 µF, 35 V,+/- 10%, X7R, AEC-Q200 Grade 1, 0603", Cap_Case=0603, Manufacturer=TDK, Supplier Part Number 1=445-174339-1-ND, TempCo=X7R, Tolerance_%=10%, Value2=35V, ValueDisplayed=1µF
C100 C101 C123 C125 C126: library part CMP-0008646-2, "CAP, CERM, 47 uF, 25 V, +/- 20%, JB, 1206", Cap_Case=1206, Manufacturer=TDK, Supplier Part Number 1=445-11717-1-ND, TempCo=JB, Tolerance_%=20%, Value1=Unknown, Value2=25V, ValueDisplayed=47uF
C103 C107 C132 C138 C139: library part CMP-0084680-1, "CAP, CERM, 22 µF, 25 V,+/- 20%, X5R, AEC-Q200 Grade 3, 0805", Cap_Case=0805, Manufacturer=MuRata, TempCo=X5R, Tolerance_%=20%, Value2=25V, ValueDisplayed=22µF
C110 C111 C112 C113: library part CMP-0081159-1, "CAP, CERM, 22 µF, 16 V,+/- 20%, X5R, 0603", Cap_Case=0603, Manufacturer=Samsung, Supplier Part Number 1=1276-7076-1-ND, TempCo=X5R, Tolerance_%=20%, Value2=16V, ValueDisplayed=22µF
C135 C136: library part CMP-0007860-1, "CAP, CERM, 4.7 uF, 50 V, +/- 10%, X6S, 0805", Cap_Case=0805, Manufacturer=TDK, Supplier Part Number 1=445-7599-1-ND, TempCo=X6S, Tolerance_%=10%, Value1="0.002346 ohm", Value2=50V, ValueDisplayed=4.7uF
D1 D2 D3 D4: library part CMP-0006013-3, "Diode, Zener, 9.1 V, 0.18 W, AEC-Q101, SOT-323", Manufacturer="NXP Semiconductor", Power_W=180mW, Value1=0.18W
D5: library part CMP-0089118-1, "Diode Array 1 Pair Series Connection Standard 100V 215mA Surface Mount SC-70, SOT-323", Digikey Part Number=SBAV99WT1GOSCT-ND, Forward Current=215mA, Manufacturer="On Semiconductor", Max Surge Forward Current=0.5A, Mouser Part Number=863-SBAV99WT1G, Operating Temperature Range="-65°C to +150°C", Peak Reverse Current=1uA, ValueDisplayed=1.5pF
D8: library part CMP-0002894-2, "LED, Green, SMD", Color=green, Manufacturer="Wurth Elektronik", Value1=W, Value2=2V
FB1 FB2: library part CMP-0003237-1, "Ferrite Bead, 120 ohm @ 100 MHz, 1.2 A, 0402", Manufacturer="Wurth Elektronik", Supplier Part Number 1=732-2366-1-ND, Value1="0.09 ohm", Value2=1.2A, ValueDisplayed="120 ohm"
FID1 FID2 FID3 FID4 FID5 FID6: library part CMP-0077181-1, "Fiducial mark.  There is nothing to buy or mount.", Manufacturer=N/A
H1 H2 H3: library part CMP-0003617-1, "Machine Screw, Round, #4-40 x 1/4, Nylon, Philips panhead", Manufacturer="B&F Fastener Supply", Supplier Part Number 1=H542-ND
J1 J4 J5: library part CMP-0079044-1, "Terminal Block, 5.08mm, 2x1, R/A, TH", Color=Green, Current_A=20A, Manufacturer="Wurth Elektronik", Supplier Part Number 1=732-10995-ND, Voltage_V=300V
J2 J6: library part CMP-0079043-1, "Terminal Block, 5.08mm, 3x1, R/A, TH", Color=Green, Current_A=20A, Manufacturer="Wurth Elektronik", Supplier Part Number 1=732-10996-ND, Voltage_V=300V
J3 J7 J9 J10 J11 J12 J13 J14: library part CMP-0075483-1, "Header, 100mil, 2x1, Gold, TH", Manufacturer=Samtec, Supplier Part Number 1=SAM8736-ND
J8: library part CMP-0075558-1, "Header(Shrouded), 19.7mil, 30x2, Gold, SMT", Manufacturer=Samtec, Supplier Part Number 1=SAM8185-ND
J17: library part CMP-0003814-2, "C2000 controlCARD-120HSEC connector, SMT", Manufacturer=Samtec
J18: library part CMP-0081902-1, "FPC Connector, 0.5mm, 22 Pos, R/A, Tin, SMT", Color=Black, Current_A=500mA, Manufacturer="Wurth Elektronik", Supplier Part Number 1=732-6003-1-ND, Voltage_V=50V
J19: library part CMP-0075524-1, "Receptacle, 0.5 mm, 30x2, Gold, TH", Color=Black, Manufacturer=Samtec, Supplier Part Number 1=SAM8180-ND
K1 K4 K5 K6 K7 K8 K9: library part CMP-0095654-1, Digikey Part Number=TLP3420(TPFCT-ND, Input Current=7.5mA, Manufacturer=Toshiba, Mouser Part Number=757-TLP3420TPF, On State Resistance=8Ω, Operating Temperature Range="-20°C to +85°C", Voltage_Isolation_Vrms=500Vrms
K2 K3: library part CMP-0080719-2, "Relay, SPST-NO (1 Form A), 0.65 A, SMD", Contact Rating_A=650mA, Manufacturer=Toshiba, Supplier Part Number 1=TLP3409S(TPECT-ND
LBL1: library part CMP-0003625-1, "Thermal Transfer Printable Labels, 0.650\" W x 0.200\" H - 10,000 per roll", Manufacturer=Brady, Supplier Part Number 1=97C5133
Logo1: library part CMP-0074844-1
Logo2: library part CMP-0074838-1, "Texas Instrument Corporate Signature"
Logo3: library part CMP-0074847-1, "FCC_disclaimer"
Logo4: library part CMP-0074769-3, Manufacturer="Texas Instruments"
R1 R2 R18 R19: library part CMP-0021141-3, "RES, 2.00, 1%, 0.125 W, AEC-Q200 Grade 0, 0805", Manufacturer=Vishay-Dale, Power_W=125mW, Supplier Part Number 1=541-2.00CCCT-ND, TempCo="100 ppm/C", Tolerance_%=1%, Value2=0.125W, Value_Code=2R00, ValueDisplayed=2.00
R3: library part CMP-0022371-4, "RES, 3.01 k, 1%, 0.1 W, AEC-Q200 Grade 0, 0603", Manufacturer=Vishay-Dale, Power_W=100mW, Supplier Part Number 1=541-3.01KHCT-ND, TempCo="100 ppm/C", Tolerance_%=1%, Value2=0.1W, Value_Code=3k01, ValueDisplayed=3.01k
R4 R5 R6 R12 R13 R14 R15 R16 R17 R72 R73 R74 R85 R96 R97 R98 R101 R102: library part CMP-0021342-3, "RES, 59.0 k, 1%, 0.125 W, AEC-Q200 Grade 0, 0805", Manufacturer=Vishay-Dale, Power_W=125mW, Supplier Part Number 1=541-59.0KCCT-ND, TempCo="100 ppm/C", Tolerance_%=1%, Value2=0.125W, Value_Code=59k0, ValueDisplayed=59.0k
R7 R8 R11 R83 R84: library part CMP-0022268-3, "RES, 2.00 k, 1%, 0.1 W, 0603", Manufacturer=Vishay-Dale, Power_W=100mW, Supplier Part Number 1=541-2.00KHCT-ND, TempCo="100 ppm/C", Tolerance_%=1%, Value2=0.1W, Value_Code=2k00, ValueDisplayed=2.00k
R9 R10 R20 R21 R53 R65 R67 R68 R69 R70 R75 R76 R77 R78 R105 R107 R115 R116 R117 R118 R120 R125 R126 R127 R135 R150 R152 R153 R159 R160 R230: library part CMP-0026748-1, "RES, 10.0 k, 1%, 0.063 W, AEC-Q200 Grade 0, 0402", Manufacturer="KOA Speer", Power_W=63mW, Supplier Part Number 1=660-RK73H1ETTP1002F, TempCo="100 ppm/C", Tolerance_%=1%, Value2=0.063W, Value_Code=10k0, ValueDisplayed=10.0k
R22 R23 R30 R33 R34 R35 R36 R37 R38 R57 R60 R61 R64 R66 R88 R90 R112 R163 R167 R176: library part CMP-0026071-2, "RES, 1.00 k, 1%, 0.063 W, 0402", Manufacturer=Vishay-Dale, Power_W=63mW, Supplier Part Number 1=541-1.00KLCT-ND, TempCo="100 ppm/C", Tolerance_%=1%, Value2=0.063W, Value_Code=1k00, ValueDisplayed=1.00k
R24: library part CMP-0015029-2, "RES, 2.00, 1%, 0.5 W, AEC-Q200 Grade 0, 1210", Manufacturer=Panasonic, Power_W=500mW, Supplier Part Number 1=P17258CT-ND, TempCo="100 ppm/C", Tolerance_%=1%, Value2=0.5W, Value_Code=2R00, ValueDisplayed=2.00
R25: library part CMP-0020835-3, "RES, 100, 1%, 0.125 W, AEC-Q200 Grade 0, 0805", Manufacturer=Vishay-Dale, Power_W=125mW, Supplier Part Number 1=541-100CCT-ND, TempCo="100 ppm/C", Tolerance_%=1%, Value2=0.125W, Value_Code=100R, ValueDisplayed=100
R26: library part CMP-0020834-2, "RES, 100 k, 1%, 0.125 W, 0805", Manufacturer=Vishay-Dale, Power_W=125mW, Supplier Part Number 1=541-100KCCT-ND, TempCo="100 ppm/C", Tolerance_%=1%, Value2=0.125W, Value_Code=100k
R27 R28 R31 R32 R47 R48 R49 R50 R51 R54 R55 R62 R63 R71 R79 R81 R87 R89 R94 R99 R104 R114 R119 R128 R129 R134 R142 R228: library part CMP-0026822-3, "RES, 0, 5%, 0.063 W, AEC-Q200 Grade 0, 0402", Manufacturer=Vishay-Dale, Power_W=63mW, Supplier Part Number 1=541-0.0JCT-ND, TempCo="200 ppm/C", Tolerance_%=5%, Value2=0.063W, Value_Code=0000, ValueDisplayed=0
R29: library part CMP-0126086-1, "2 Ohms ±1% 0.5W, 1/2W Chip Resistor Wide 2516 (6440 Metric), 1625 Current Sense, Moisture Resistant, Non-Inductive Metal Foil", Digikey Part Number=804-1119-1-ND, Manufacturer="VPG Foil Resistors", Operating Temperature Range="-55°C to +125°C", Power_W=500mW, TempCo=2ppm/°C, Tolerance_%=1%
R39 R44: library part CMP-0021039-1, "RES, 200, 1%, 0.125 W, 0805", Manufacturer=Vishay-Dale, Power_W=125mW, Supplier Part Number 1=541-200CCT-ND, TempCo="100 ppm/C", Tolerance_%=1%, Value2=0.125W, Value_Code=200R, ValueDisplayed=200
R40 R41 R45 R46 R52 R56 R58 R59 R91 R92 R93 R95 R103 R111 R113 R121 R123 R124 R130 R138 R229 R233: library part CMP-0026763-1, "RES, 100, 1%, 0.063 W, AEC-Q200 Grade 0, 0402", Manufacturer="Stackpole Electronics Inc", Power_W=63mW, Supplier Part Number 1=RMCF0402JT100RCT-ND, TempCo="100 ppm/C", Tolerance_%=1%, Value2=0.063W, Value_Code=100R, ValueDisplayed=100
R42: library part CMP-0021721-3, "RES, 45.3 k, 1%, 0.125 W, AEC-Q200 Grade 0, 0805", Manufacturer=Panasonic, Power_W=125mW, Supplier Part Number 1=P45.3KCCT-ND, TempCo="100 ppm/C", Tolerance_%=1%, Value2=0.125W, Value_Code=45k3, ValueDisplayed=45.3k
R43: library part CMP-0088945-1, "5 kOhms ±1% 0.125W, 1/8W Chip Resistor 0805 (2012 Metric) Automotive AEC-Q200 Thick Film", Digikey Part Number=541-4321-1-ND, Manufacturer="Vishay Dale", Mouser Part Number=71-CRCW0805-5K, Operating Temperature Range="-55°C to +155°C", Power_W=125mW, TempCo=100ppm/°C, Tolerance_%=1%
R80 R82: library part CMP-0021613-3, "RES, 2.00 k, 1%, 0.125 W, AEC-Q200 Grade 0, 0805", Manufacturer=Panasonic, Power_W=125mW, Supplier Part Number 1=P2.00KCCT-ND, TempCo="100 ppm/C", Tolerance_%=1%, Value2=0.125W, Value_Code=2k00, ValueDisplayed=2.00k
R86 R161: library part CMP-0026178-1, "RES, 22.1 k, 1%, 0.063 W, 0402", Manufacturer=Vishay-Dale, Power_W=63mW, Supplier Part Number 1=541-22.1KLCT-ND, TempCo="100 ppm/C", Tolerance_%=1%, Value2=0.063W, Value_Code=22k1, ValueDisplayed=22.1k
R100 R110 R155 R204 R208: library part CMP-0026727-1, "RES, 1.00 M, 1%, 0.063 W, 0402", Manufacturer="Yageo America", Power_W=63mW, Supplier Part Number 1=311-1.00MLRCT-ND, TempCo="100 ppm/C", Tolerance_%=1%, Value2=0.063W, Value_Code=1M00, ValueDisplayed=1.00M
R106: library part CMP-0026370-1, "RES, 412, 1%, 0.063 W, 0402", Manufacturer=Vishay-Dale, Power_W=63mW, Supplier Part Number 1=541-412LCT-ND, TempCo="100 ppm/C", Tolerance_%=1%, Value2=0.063W, Value_Code=412R, ValueDisplayed=412
R108 R232: library part CMP-0026414-1, "RES, 4.99 k, 1%, 0.063 W, 0402", Manufacturer=Vishay-Dale, Power_W=63mW, Supplier Part Number 1=541-4.99KLCT-ND, TempCo="100 ppm/C", Tolerance_%=1%, Value2=0.063W, Value_Code=4k99, ValueDisplayed=4.99k
R109: library part CMP-0026227-1, "RES, 2.00 k, 1%, 0.063 W, 0402", Manufacturer=Vishay-Dale, Power_W=63mW, Supplier Part Number 1=541-2.00KLCT-ND, TempCo="100 ppm/C", Tolerance_%=1%, Value2=0.063W, Value_Code=2k00, ValueDisplayed=2.00k
R122: library part CMP-0026029-3, "RES, 15.8 k, 1%, 0.063 W, AEC-Q200 Grade 0, 0402", Manufacturer=Vishay-Dale, Power_W=63mW, Supplier Part Number 1=541-15.8KLCT-ND, TempCo="100 ppm/C", Tolerance_%=1%, Value2=0.063W, Value_Code=15k8, ValueDisplayed=15.8k
R131 R133 R137 R139 R140 R144 R146 R165 R166 R169 R170 R171 R172 R173 R174 R175 R177 R178 R179 R180 R181 R182 R183 R184 R185 R186 R187 R188 R189 R190 R191 R192 R197 R199 R201 R203 R206 R214 R215 R216 R217 R218 R219 R220 R221 R222 R223 R224 R225 R226 R227 R231: library part CMP-0025963-3, "RES, 10.0, 1%, 0.063 W, AEC-Q200 Grade 0, 0402", Manufacturer=Vishay-Dale, PartNumber=CRCW040210R0FKED, Power_W=63mW, Supplier Part Number 1=541-10.0LCT-ND, TempCo="100 ppm/C", Tolerance_%=1%, Value2=0.063W, Value_Code=10R0, ValueDisplayed=10.0
R132 R136 R143 R145 R193 R194 R195 R196 R198 R200 R202 R205 R207 R209: library part CMP-0025963-3, "RES, 10.0, 1%, 0.063 W, AEC-Q200 Grade 0, 0402", Manufacturer=Vishay-Dale, Power_W=63mW, Supplier Part Number 1=541-10.0LCT-ND, TempCo="100 ppm/C", Tolerance_%=1%, Value2=0.063W, Value_Code=10R0, ValueDisplayed=10.0
R141: library part CMP-0026071-3, "RES, 1.00 k, 1%, 0.063 W, AEC-Q200 Grade 0, 0402", Manufacturer=Vishay-Dale, Power_W=63mW, Supplier Part Number 1=541-1.00KLCT-ND, TempCo="100 ppm/C", Tolerance_%=1%, Value2=0.063W, Value_Code=1k00, ValueDisplayed=1.00k
R147 R157: library part CMP-0026744-1, "RES, 82.0 k, 1%, 0.063 W, 0402", Manufacturer="Yageo America", Power_W=63mW, Supplier Part Number 1=311-82.0KLRCT-ND, TempCo="100 ppm/C", Tolerance_%=1%, Value2=0.063W, Value_Code=82k0, ValueDisplayed=82.0k
R148 R158: library part CMP-0025967-2, "RES, 110 k, 1%, 0.063 W, 0402", Manufacturer=Vishay-Dale, Power_W=63mW, Supplier Part Number 1=541-110KLCT-ND, TempCo="100 ppm/C", Tolerance_%=1%, Value2=0.063W, Value_Code=110k
R149: library part CMP-0026739-1, "RES, 4.70 k, 1%, 0.0625 W, 0402", Manufacturer="Yageo America", Power_W=62.5mW, Supplier Part Number 1=311-4.7KLRCT-ND, TempCo="100 ppm/C", Tolerance_%=1%, Value2=0.0625W, Value_Code=4k70, ValueDisplayed=4.70k
R151: library part CMP-0026441-2, "RES, 52.3 k, 1%, 0.063 W, AEC-Q200 Grade 0, 0402", Manufacturer=Vishay-Dale, Power_W=63mW, Supplier Part Number 1=541-52.3KLCT-ND, TempCo="100 ppm/C", Tolerance_%=1%, Value2=0.063W, Value_Code=52k3, ValueDisplayed=52.3k
R154 R162: library part CMP-0026003-2, "RES, 13.0 k, 1%, 0.063 W, 0402", Manufacturer=Vishay-Dale, Power_W=63mW, Supplier Part Number 1=541-13.0KLCT-ND, TempCo="100 ppm/C", Tolerance_%=1%, Value2=0.063W, Value_Code=13k0, ValueDisplayed=13.0k
R156 R234: library part CMP-0026728-1, "RES, 220 k, 1%, 0.0625 W, 0402", Manufacturer="Yageo America", Power_W=62.5mW, Supplier Part Number 1=311-220KLRCT-ND, TempCo="100 ppm/C", Tolerance_%=1%, Value2=0.0625W, Value_Code=220k
R164 R168: library part CMP-0026231-2, "RES, 2.20 k, 1%, 0.063 W, AEC-Q200 Grade 0, 0402", Manufacturer=Vishay-Dale, Power_W=63mW, Supplier Part Number 1=541-2.20KLCT-ND, TempCo="100 ppm/C", Tolerance_%=1%, Value2=0.063W, Value_Code=2k20, ValueDisplayed=2.20k
R210 R211 R212 R213: library part CMP-0023338-2, "RES, 0.2, 1%, 0.2 W, AEC-Q200 Grade 0, 0603", Manufacturer=Vishay-Dale, Power_W=200mW, Supplier Part Number 1=RCWE.2CCT-ND, TempCo="100 ppm/C", Tolerance_%=1%, Value2=0.2W, Value_Code=R200, ValueDisplayed=0.2
RN1: library part CMP-0126296-1, "2k, 18k Ohm ±0.005% 500mW Power Per Element Voltage Divider 2 Resistor Network/Array ±0.2ppm/°C Radial - 3 Leads", Digikey Part Number=804-Y0115V0030VV9L-ND, Manufacturer="VPG Foil Resistors", Number Of Resistors=2, Operating Temperature Range="-55°C to +125°C", Power Per Resistor=0.5W, Power_W=1W, TempCo=0.2ppm/°C, Tolerance_%=0.005%
RN2 RN3 RN6 RN7: library part CMP-0123029-1, "Automotive low-noise matched thin-film resistor divider network with 1kΩ fixed input 8-SOT-23-THIN -40 to 125", Manufacturer="Texas Instruments", Number Of Resistors=4, Operating Temperature Range="-40°C to +125°C", TempCo=18ppm/°C, Tolerance_%=2%
SH-J1 SH-J2 SH-J3 SH-J4 SH-J5 SH-J6: library part CMP-0003761-2, "Shunt, 2.54mm, Gold, Black", Manufacturer="Wurth Elektronik", Supplier Part Number 1=732-2678-ND
TP1 TP2: library part CMP-0055137-2, "Test Point, Miniature, Red, TH", Color=Red, Manufacturer="Keystone Electronics", Supplier Part Number 1=36-5000-ND
TP3 TP5 TP6: library part CMP-0055138-1, "Test Point, Miniature, Black, TH", Color=Black, Manufacturer=Keystone, Supplier Part Number 1=36-5001-ND
U1 U2 U3 U4: library part CMP-0089642-1, "85V, 250 mA Output Current, Precision Operational Amplifier", Input Bias Current=0.00001uA, Input Offset Voltage=0.01mV, Manufacturer="Texas Instruments", Max Dual Supply Voltage=42.5V, Max Supply Voltage=85V, Min Dual Supply Voltage=5V, Min Supply Voltage=10V, Nominal Supply Current=3.25mA, Operating Temperature Range="-40°C to +150°C", Output Current Per Channel=250mA, Voltage Gain=120dB
U5 U6: library part CMP-0043744-3, "High Voltage (100V), High-Current (50mA) Operational Amplifiers, G=1 Stable, DDA0008J (HSOIC-8)", Alternate Manufacturer="Texas Instruments", Alternate PartNumber=OPA454AIDDA, Operating Temperature Range="-55 to 125 C", Rating=Catalog, Total Supply Voltage(Max)(+5V is 5, +/-5V is 10)=100, Total Supply Voltage(Min)(+5V is 5, +/-5V is 10)=10
U7: library part CMP-0126324-1, "85V high speed (100V/µs) to power (400µA) ratio precision op-amp in small package 5-SOT-23 -40 to 125", Digikey Part Number=296-OPA596DBVRTR-ND, Input Bias Current=5pA, Input Offset Voltage=0.2mV, Manufacturer="Texas Instruments", Max Dual Supply Voltage=42.5V, Max Supply Voltage=85V, Min Dual Supply Voltage=4V, Min Supply Voltage=8V, Mouser Part Number=595-OPA596DBVR, Nominal Supply Current=420uA, Operating Temperature Range="-40°C to +125°C", Output Current Per Channel=30mA, Voltage Gain=140dB
U8 U10 U14 U19 U30: library part CMP-0096836-1, "36-V, 5-MHz, Low-Noise, Zero-Drift, MUX-Friendly, Precision Op Amps", Digikey Part Number=296-OPA2182ID-ND, Input Bias Current=0.007uA, Input Offset Voltage=0.00045mV, Manufacturer="Texas Instruments", Max Dual Supply Voltage=18V, Max Supply Voltage=36V, Min Dual Supply Voltage=2.25V, Min Supply Voltage=4.5V, Mouser Part Number=595-OPA2182ID, Nominal Supply Current=0.85mA, Operating Temperature Range="-40°C to +125°C", Output Current Per Channel=65mA, Voltage Gain=170dB
U9 U15: library part CMP-0120565-1, "Low-Noise, Wide-Bandwidth, Precision Programmable Gain Instrumentation Amplifier", Input Bias Current=0.0005uA, Input Offset Voltage=0.015mV, Manufacturer="Texas Instruments", Max Dual Supply Voltage=18V, Max Supply Voltage=36V, Min Dual Supply Voltage=4V, Min Supply Voltage=8V, Nominal Supply Current=3mA, Operating Temperature Range="-40°C to +125°C", Output Current Per Channel=45mA, Voltage Gain=0.000125-0.016V/mV
U11 U39: library part CMP-0126280-1, "36-V, latch-up immune, 1: 1 (SPST) 2 channel precision switch with 1.8V logic (active high) 10-VSSOP -40 to 125", Digikey Part Number=296-TMUX6221DGSRCT-ND, Manufacturer="Texas Instruments", Max Supply Voltage=36V, Min Supply Voltage=4.5V, Mouser Part Number=595-TMUX6221DGSR, On State Resistance=2.1Ω, Operating Temperature Range="-40°C to +125°C"
U12: library part CMP-0121034-1, "36 V High-Speed Comparators with Separate Input and Output Supplies", Input Bias Current=0.0005uA, Input Offset Voltage=0.5mV, Manufacturer="Texas Instruments", Max Supply Voltage=36V, Min Supply Voltage=2.7V, Nominal Supply Current=70-95uA, Operating Temperature Range="-40°C to +125°C", Output Current Per Channel=30mA
U13: library part CMP-0126339-1, "Zero-Drift Amplifier 1 Circuit Rail-to-Rail SOT-23-5", Digikey Part Number=296-OPA182IDBVRCT-ND, Input Bias Current=50pA, Input Offset Voltage=0.45uV, Manufacturer="Texas Instruments", Max Dual Supply Voltage=36V, Max Supply Voltage=18V, Min Dual Supply Voltage=2.25V, Min Supply Voltage=4.5V, Mouser Part Number=595-OPA182IDBVR, Nominal Supply Current=0.85mA, Operating Temperature Range="-40°C to +125°C", Output Current Per Channel=65mA, Voltage Gain=170dB
U16 U17 U20: library part CMP-0126080-1, "36-V low Ron 2: 1 one channel multiplexer with 1.8-V logic control 8-WSON -40 to 125", Digikey Part Number=296-TMUX6219RQXRCT-ND, Manufacturer="Texas Instruments", Max Supply Voltage=36V, Min Supply Voltage=4.5V, Mouser Part Number=595-TMUX6219RQXR, Nominal Supply Current=30uA, On State Resistance=2.1Ω, Operating Temperature Range="-40°C to +125°C"
U18 U25: library part CMP-0123006-1, "36-V, low-RON, 2: 1 (SPDT) two-channel precision switch with latch-up immunity and 1.8-V logic 16-WQFN -40 to 125", Digikey Part Number=296-TMUX6236RUMRCT-ND, Manufacturer="Texas Instruments", Max Supply Voltage=36V, Min Supply Voltage=4.5V, Mouser Part Number=595-TMUX6236RUMR, On State Resistance=2Ω, Operating Temperature Range="-40°C to +125°C"
U21 U22: library part CMP-0122930-1, "36-V low RON, 1: 1, four-channel, multiplexer with 1.8-V logic control 16-WQFN -40 to 125", Digikey Part Number=296-TMUX6212RUMRTR-ND, Manufacturer="Texas Instruments", Max Supply Voltage=36V, Min Supply Voltage=4.5V, Mouser Part Number=595-TMUX6212RUMR, On State Resistance=2Ω, Operating Temperature Range="-40°C to +125°C"
U23 U26: library part CMP-0094311-1, "Low-Voltage Translating, 16-Bit I2C-Bus, SMBus I/O Expander with Interrupt Output, Reset, and Agile I/O Configuration Registers", Frequency_Fixed=1MHz, Manufacturer="Texas Instruments", Max Supply Voltage=3.6V, Min Supply Voltage=1.08V, Nominal Supply Current=2-11uA, Operating Temperature Range="to +125°C"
